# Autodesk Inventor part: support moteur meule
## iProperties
Shininess: 64.0
Length Units: 11269
Angle Units: 11279
Time Units: 11290
Mass Units: 11283
Length Display Precision: 3
Angle Display Precision: 2
Compacted: True
Part Number: support moteur meule
Document SubType Name: Modeling
Created: 2005-01
Material: Par défaut
Designer: LEGERET Philippe
Density: 0.0
Volumn: 0.0
Area: 0.0
PropertySet Name: Model Information
Control State: 0
Master: False
Checked Out: False
Author: LEGERET Philippe
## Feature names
1. Extrusion1
2. Extrusion2
